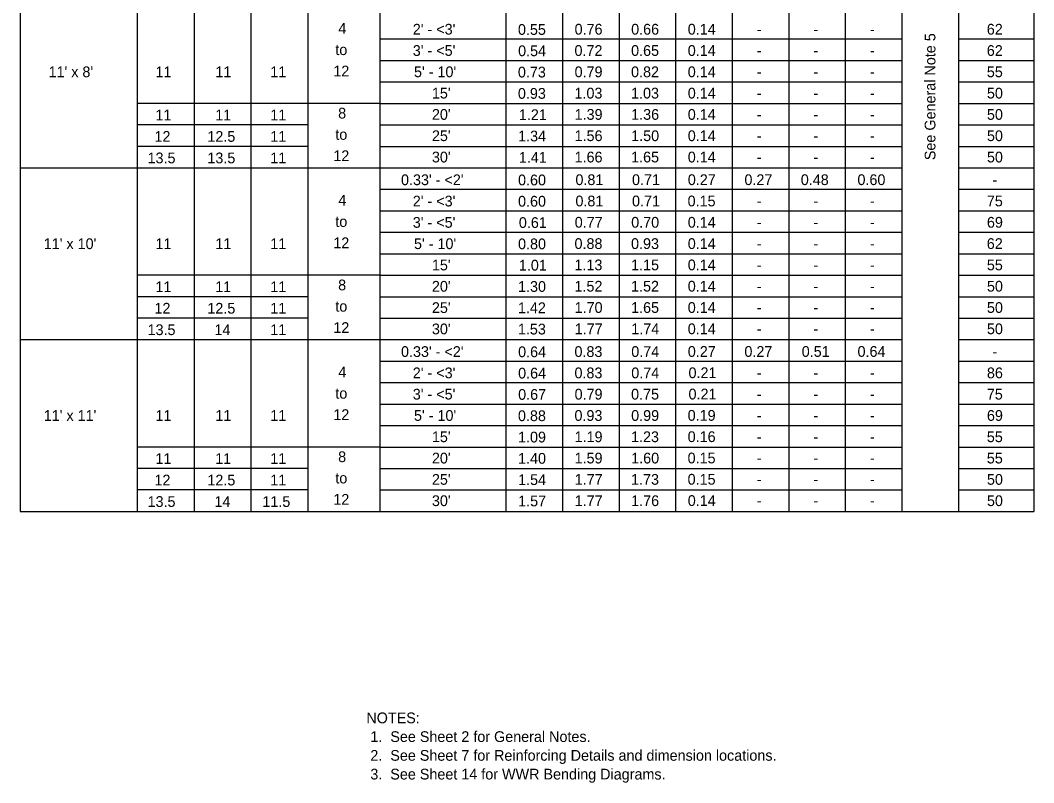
# Model space of a CAD drawing. Extents: x 10351.18 to 10353.4, y 76371.55 to 76372.62.
# Drawn here: x 10351.832 to 10352.427, y 76371.801 to 76372.249 of the extents above; entities that cross this region are included whole.
import ezdxf

# ---------------------------------------------------------------- set-up
doc = ezdxf.new("R2010")
doc.units = 0
doc.layers.add('AdhocPoint_dp', color=7, linetype='Continuous')
doc.layers.add('PlotBorder_dp', color=7, linetype='Continuous')

msp = doc.modelspace()

# ---------------------------------------------------------------- linework, layer by layer
at = {"layer": 'PlotBorder_dp'}
for p, q in [((10351.83244, 76372.53475), (10351.83244, 76371.96053)), ((10352.42718, 76372.53475), (10352.42718, 76371.96053)), ((10351.90108, 76372.51488), (10351.90108, 76371.96053)), ((10352.04352, 76372.51488), (10352.04352, 76371.96053)), ((10352.1174, 76372.51488), (10352.1174, 76371.96053)), ((10352.38299, 76372.51488), (10352.38299, 76371.96053)), ((10351.93444, 76372.50228), (10351.93444, 76371.96053)), ((10351.9678, 76372.50228), (10351.9678, 76371.96053)), ((10352.00116, 76372.50228), (10352.00116, 76371.96053)), ((10352.1506, 76372.47713), (10352.1506, 76371.96053)), ((10352.1838, 76372.47713), (10352.1838, 76371.96053)), ((10352.217, 76372.47713), (10352.217, 76371.96053)), ((10352.2502, 76372.47713), (10352.2502, 76371.96053)), ((10352.28339, 76372.47713), (10352.28339, 76371.96053)), ((10352.28339, 76372.47713), (10352.28339, 76371.96053)), ((10352.31659, 76372.47713), (10352.31659, 76371.96053)), ((10352.34979, 76372.47713), (10352.34979, 76371.96053)), ((10352.04352, 76372.23773), (10352.34979, 76372.23773)), ((10352.38299, 76372.23772), (10352.42718, 76372.23772)), ((10352.04352, 76372.22513), (10352.34979, 76372.22513)), ((10352.38299, 76372.22512), (10352.42718, 76372.22512)), ((10352.04352, 76372.21253), (10352.34979, 76372.21253)), ((10352.38299, 76372.21252), (10352.42718, 76372.21252)), ((10352.04352, 76372.19993), (10351.90108, 76372.19993)), ((10352.04352, 76372.19993), (10352.34979, 76372.19993)), ((10352.38299, 76372.19992), (10352.42718, 76372.19992)), ((10352.00116, 76372.18733), (10351.90108, 76372.18733)), ((10352.04352, 76372.18733), (10352.34979, 76372.18733)), ((10352.38299, 76372.18732), (10352.42718, 76372.18732)), ((10352.00116, 76372.17473), (10351.90108, 76372.17473)), ((10352.04352, 76372.17473), (10352.34979, 76372.17473)), ((10352.38299, 76372.17472), (10352.42718, 76372.17472)), ((10351.83244, 76372.16213), (10352.34979, 76372.16213)), ((10352.04414, 76372.16212), (10352.11631, 76372.16212)), ((10352.04414, 76372.16212), (10352.11631, 76372.16212)), ((10352.38299, 76372.16212), (10352.42718, 76372.16212)), ((10352.04352, 76372.14953), (10352.34979, 76372.14953)), ((10352.38299, 76372.14952), (10352.42718, 76372.14952)), ((10352.04352, 76372.13693), (10352.34979, 76372.13693)), ((10352.38299, 76372.13692), (10352.42718, 76372.13692)), ((10352.04352, 76372.12433), (10352.34979, 76372.12433)), ((10352.38299, 76372.12432), (10352.42718, 76372.12432)), ((10352.04352, 76372.11173), (10352.34979, 76372.11173)), ((10352.38299, 76372.11172), (10352.42718, 76372.11172)), ((10352.04352, 76372.09913), (10351.90108, 76372.09913)), ((10352.04352, 76372.09913), (10352.34979, 76372.09913)), ((10352.38299, 76372.09912), (10352.42718, 76372.09912)), ((10352.00116, 76372.08653), (10351.90108, 76372.08653)), ((10352.04352, 76372.08653), (10352.34979, 76372.08653)), ((10352.38299, 76372.08652), (10352.42718, 76372.08652)), ((10352.00116, 76372.07393), (10351.90108, 76372.07393)), ((10352.04352, 76372.07393), (10352.34979, 76372.07393)), ((10352.38299, 76372.07392), (10352.42718, 76372.07392)), ((10351.83244, 76372.06133), (10352.34979, 76372.06133)), ((10352.04414, 76372.06132), (10352.11631, 76372.06132)), ((10352.04414, 76372.06132), (10352.11631, 76372.06132)), ((10352.04414, 76372.06132), (10352.11631, 76372.06132)), ((10352.38299, 76372.06132), (10352.42718, 76372.06132)), ((10352.04352, 76372.04873), (10352.34979, 76372.04873)), ((10352.38299, 76372.04872), (10352.42718, 76372.04872)), ((10352.04352, 76372.03613), (10352.34979, 76372.03613)), ((10352.38299, 76372.03612), (10352.42718, 76372.03612)), ((10352.04352, 76372.02353), (10352.34979, 76372.02353)), ((10352.38299, 76372.02352), (10352.42718, 76372.02352)), ((10352.04352, 76372.01093), (10352.34979, 76372.01093)), ((10352.38299, 76372.01092), (10352.42718, 76372.01092)), ((10352.04352, 76371.99833), (10351.90108, 76371.99833)), ((10352.04352, 76371.99833), (10352.34979, 76371.99833)), ((10352.38299, 76371.99832), (10352.42718, 76371.99832)), ((10352.00116, 76371.98573), (10351.90108, 76371.98573)), ((10352.04352, 76371.98573), (10352.34979, 76371.98573)), ((10352.38299, 76371.98572), (10352.42718, 76371.98572)), ((10352.00116, 76371.97313), (10351.90108, 76371.97313)), ((10352.04352, 76371.97313), (10352.34979, 76371.97313)), ((10352.38299, 76371.97312), (10352.42718, 76371.97312)), ((10351.83244, 76371.96053), (10352.42718, 76371.96053)), ((10352.04414, 76371.96052), (10352.11631, 76371.96052))]:
    msp.add_line(p, q, dxfattribs=at)

# ---------------------------------------------------------------- texts
at = {"layer": 'AdhocPoint_dp'}
msp.add_text('See General Note 5', height=0.0063, rotation=90, dxfattribs=at).set_placement((10352.36949, 76372.16663))
for s, p in [('11', (10351.91176, 76372.18999)), ('11', (10351.94685, 76372.18999)), ('11', (10351.97914, 76372.18999)), ('12', (10351.91119, 76372.17739)), ('12.5', (10351.94224, 76372.17739)), ('11', (10351.97914, 76372.17739)), ('13.5', (10351.90714, 76372.16479)), ('13.5', (10351.94224, 76372.16479)), ('11', (10351.97914, 76372.16479)), ('11', (10351.91176, 76372.08919)), ('11', (10351.94685, 76372.08919)), ('11', (10351.97914, 76372.08919)), ('12', (10351.91119, 76372.07659)), ('12.5', (10351.94224, 76372.07659)), ('11', (10351.97914, 76372.07659)), ('13.5', (10351.90714, 76372.06399)), ('14', (10351.94641, 76372.06399)), ('11', (10351.97914, 76372.06399)), ('11', (10351.91176, 76371.98839)), ('11', (10351.94685, 76371.98839)), ('11', (10351.97914, 76371.98839)), ('12', (10351.91119, 76371.97579)), ('12.5', (10351.94224, 76371.97579)), ('11', (10351.97914, 76371.97579)), ('13.5', (10351.90714, 76371.96319)), ('14', (10351.94641, 76371.96319)), ('11.5', (10351.97452, 76371.96319))]:
    msp.add_text(s, height=0.0063, dxfattribs=at).set_placement(p)
at = {"layer": 'PlotBorder_dp'}
for s, p in [('4', (10352.0191, 76372.24078)), ("2' - <3'", (10352.06278, 76372.2403)), ('0.55', (10352.1245, 76372.24014)), ('0.76', (10352.15774, 76372.2403)), ('0.66', (10352.19094, 76372.2403)), ('0.14', (10352.22416, 76372.2403)), ('62', (10352.39964, 76372.2403)), ('-', (10352.26467, 76372.2403)), ('-', (10352.29788, 76372.2403)), ('-', (10352.33106, 76372.2403)), ('to', (10352.01732, 76372.22828)), ("3' - <5'", (10352.06278, 76372.2278)), ('0.54', (10352.1246, 76372.22764)), ('0.72', (10352.15768, 76372.2278)), ('0.65', (10352.1909, 76372.2278)), ('0.14', (10352.22416, 76372.2278)), ('62', (10352.39964, 76372.2278)), ('-', (10352.26467, 76372.2278)), ('-', (10352.29788, 76372.2278)), ('-', (10352.33106, 76372.2278)), ("11' x 8'", (10351.84905, 76372.2153)), ('11', (10351.91182, 76372.2153)), ('11', (10351.94691, 76372.2153)), ('11', (10351.97915, 76372.2153)), ('12', (10352.01615, 76372.21578)), ("5' - 10'", (10352.06349, 76372.2153)), ('0.73', (10352.12447, 76372.21514)), ('0.79', (10352.15774, 76372.2153)), ('0.82', (10352.19088, 76372.2153)), ('0.14', (10352.22416, 76372.2153)), ('55', (10352.39967, 76372.2153)), ('-', (10352.26467, 76372.2153)), ('-', (10352.29788, 76372.2153)), ('-', (10352.33106, 76372.2153)), ("15'", (10352.07401, 76372.2028)), ('1.03', (10352.15767, 76372.2028)), ('1.03', (10352.19087, 76372.2028)), ('0.14', (10352.22416, 76372.2028)), ('50', (10352.39972, 76372.2028)), ('0.93', (10352.12447, 76372.20264)), ('-', (10352.26467, 76372.2028)), ('-', (10352.29788, 76372.2028)), ('-', (10352.33106, 76372.2028)), ('8', (10352.01899, 76372.19106)), ("20'", (10352.07401, 76372.1903)), ('1.21', (10352.12504, 76372.19014)), ('1.39', (10352.15774, 76372.1903)), ('1.36', (10352.19094, 76372.1903)), ('0.14', (10352.22416, 76372.1903)), ('-', (10352.26467, 76372.1903)), ('-', (10352.29788, 76372.1903)), ('-', (10352.33106, 76372.1903)), ('50', (10352.39972, 76372.1903)), ('to', (10352.01732, 76372.17856)), ("25'", (10352.07401, 76372.1778)), ('1.34', (10352.1246, 76372.17764)), ('1.56', (10352.15774, 76372.1778)), ('1.50', (10352.19096, 76372.1778)), ('0.14', (10352.22416, 76372.1778)), ('-', (10352.26467, 76372.1778)), ('-', (10352.29788, 76372.1778)), ('-', (10352.33106, 76372.1778)), ('50', (10352.39972, 76372.1778)), ('12', (10352.01615, 76372.16606)), ("30'", (10352.07401, 76372.1653)), ('1.41', (10352.12504, 76372.16514)), ('1.66', (10352.15774, 76372.1653)), ('1.65', (10352.1909, 76372.1653)), ('0.14', (10352.22416, 76372.1653)), ('-', (10352.26467, 76372.1653)), ('-', (10352.29788, 76372.1653)), ('-', (10352.33106, 76372.1653)), ('50', (10352.39972, 76372.1653)), ("0.33' - <2'", (10352.05588, 76372.15196)), ('0.60', (10352.12456, 76372.15186)), ('0.81', (10352.15824, 76372.15202)), ('0.71', (10352.19144, 76372.15202)), ('0.27', (10352.22418, 76372.15202)), ('0.27', (10352.25741, 76372.15202)), ('0.48', (10352.29049, 76372.15202)), ('0.60', (10352.32374, 76372.15202)), ('-', (10352.40298, 76372.15202)), ('4', (10352.0191, 76372.13998)), ("2' - <3'", (10352.06278, 76372.13946)), ('0.60', (10352.12456, 76372.13936)), ('0.81', (10352.15824, 76372.13952)), ('0.71', (10352.19144, 76372.13952)), ('0.15', (10352.22406, 76372.13952)), ('75', (10352.39967, 76372.13952)), ('-', (10352.26467, 76372.13952)), ('-', (10352.29788, 76372.13952)), ('-', (10352.33106, 76372.13952)), ('to', (10352.01732, 76372.12748)), ("3' - <5'", (10352.06278, 76372.12696)), ('0.61', (10352.12504, 76372.12686)), ('0.77', (10352.15782, 76372.12702)), ('0.70', (10352.19096, 76372.12702)), ('0.14', (10352.22416, 76372.12702)), ('69', (10352.39971, 76372.12702)), ('-', (10352.26467, 76372.12702)), ('-', (10352.29788, 76372.12702)), ('-', (10352.33106, 76372.12702)), ("11' x 10'", (10351.84622, 76372.11446)), ('11', (10351.91182, 76372.11446)), ('11', (10351.94691, 76372.11446)), ('11', (10351.97915, 76372.11446)), ('12', (10352.01615, 76372.11498)), ("5' - 10'", (10352.06349, 76372.11446)), ('0.80', (10352.12456, 76372.11436)), ('0.88', (10352.15769, 76372.11452)), ('0.93', (10352.19087, 76372.11452)), ('0.14', (10352.22416, 76372.11452)), ('62', (10352.39964, 76372.11452)), ('-', (10352.26467, 76372.11452)), ('-', (10352.29788, 76372.11452)), ('-', (10352.33106, 76372.11452)), ("15'", (10352.07401, 76372.10196)), ('1.01', (10352.12504, 76372.10186)), ('1.13', (10352.15767, 76372.10202)), ('1.15', (10352.1909, 76372.10202)), ('0.14', (10352.22416, 76372.10202)), ('55', (10352.39967, 76372.10202)), ('-', (10352.26467, 76372.10202)), ('-', (10352.29788, 76372.10202)), ('-', (10352.33106, 76372.10202)), ('8', (10352.01899, 76372.09026)), ("20'", (10352.07401, 76372.08946)), ('1.30', (10352.12456, 76372.08936)), ('1.52', (10352.15768, 76372.08952)), ('1.52', (10352.19088, 76372.08952)), ('0.14', (10352.22416, 76372.08952)), ('-', (10352.26467, 76372.08952)), ('-', (10352.29788, 76372.08952)), ('-', (10352.33106, 76372.08952)), ('50', (10352.39972, 76372.08952)), ('to', (10352.01732, 76372.07776)), ("25'", (10352.07401, 76372.07696)), ('1.42', (10352.12448, 76372.07686)), ('1.70', (10352.15775, 76372.07702)), ('1.65', (10352.1909, 76372.07702)), ('0.14', (10352.22416, 76372.07702)), ('-', (10352.26467, 76372.07702)), ('-', (10352.29788, 76372.07702)), ('-', (10352.33106, 76372.07702)), ('50', (10352.39972, 76372.07702)), ('12', (10352.01615, 76372.06526)), ("30'", (10352.07401, 76372.06446)), ('1.53', (10352.12447, 76372.06436)), ('1.77', (10352.15782, 76372.06452)), ('1.74', (10352.191, 76372.06452)), ('0.14', (10352.22416, 76372.06452)), ('-', (10352.26467, 76372.06452)), ('-', (10352.29788, 76372.06452)), ('-', (10352.33106, 76372.06452)), ('50', (10352.39972, 76372.06452)), ("0.33' - <2'", (10352.05588, 76372.05118)), ('0.64', (10352.1246, 76372.05103)), ('0.83', (10352.15767, 76372.05118)), ('0.74', (10352.191, 76372.05118)), ('0.27', (10352.22418, 76372.05124)), ('0.27', (10352.25741, 76372.05124)), ('0.51', (10352.29104, 76372.05124)), ('0.64', (10352.32378, 76372.05124)), ('-', (10352.40298, 76372.05118)), ('4', (10352.0191, 76372.03918)), ("2' - <3'", (10352.06278, 76372.03868)), ('0.64', (10352.1246, 76372.03853)), ('0.83', (10352.15767, 76372.03868)), ('0.74', (10352.191, 76372.03868)), ('0.21', (10352.2246, 76372.03874)), ('86', (10352.39971, 76372.03868)), ('-', (10352.26467, 76372.03874)), ('-', (10352.29788, 76372.03874)), ('-', (10352.33106, 76372.03874)), ('to', (10352.01732, 76372.02668)), ("3' - <5'", (10352.06278, 76372.02618)), ('0.67', (10352.12462, 76372.02603)), ('0.79', (10352.15774, 76372.02618)), ('0.75', (10352.1909, 76372.02618)), ('0.21', (10352.2246, 76372.02624)), ('75', (10352.39967, 76372.02618)), ('-', (10352.26467, 76372.02624)), ('-', (10352.29788, 76372.02624)), ('-', (10352.33106, 76372.02624)), ("11' x 11'", (10351.84622, 76372.01368)), ('11', (10351.91182, 76372.01368)), ('11', (10351.94691, 76372.01368)), ('11', (10351.97915, 76372.01368)), ('12', (10352.01615, 76372.01418)), ("5' - 10'", (10352.06349, 76372.01368)), ('0.88', (10352.1245, 76372.01353)), ('0.93', (10352.15767, 76372.01368)), ('0.99', (10352.19094, 76372.01368)), ('0.19', (10352.2241, 76372.01374)), ('69', (10352.39971, 76372.01368)), ('-', (10352.26467, 76372.01374)), ('-', (10352.29788, 76372.01374)), ('-', (10352.33106, 76372.01374)), ("15'", (10352.07401, 76372.00118)), ('1.09', (10352.12454, 76372.00103)), ('1.19', (10352.15774, 76372.00118)), ('1.23', (10352.19087, 76372.00118)), ('0.16', (10352.2241, 76372.00124)), ('55', (10352.39967, 76372.00118)), ('-', (10352.26467, 76372.00124)), ('-', (10352.29788, 76372.00124)), ('-', (10352.33106, 76372.00124)), ('8', (10352.01899, 76371.98946)), ("20'", (10352.07401, 76371.98868)), ('1.59', (10352.15774, 76371.98868)), ('1.60', (10352.19096, 76371.98868)), ('0.15', (10352.22406, 76371.98874)), ('55', (10352.39967, 76371.98868)), ('1.40', (10352.12456, 76371.98853)), ('-', (10352.26467, 76371.98874)), ('-', (10352.29788, 76371.98874)), ('-', (10352.33106, 76371.98874)), ('to', (10352.01732, 76371.97696)), ("25'", (10352.07401, 76371.97618)), ('1.54', (10352.1246, 76371.97603)), ('1.77', (10352.15782, 76371.97618)), ('1.73', (10352.19087, 76371.97618)), ('0.15', (10352.22406, 76371.97624)), ('-', (10352.26467, 76371.97624)), ('-', (10352.29788, 76371.97624)), ('-', (10352.33106, 76371.97624)), ('50', (10352.39972, 76371.97618)), ('12', (10352.01615, 76371.96446)), ("30'", (10352.07401, 76371.96368)), ('1.57', (10352.12462, 76371.96353)), ('1.77', (10352.15782, 76371.96368)), ('1.76', (10352.19094, 76371.96368)), ('0.14', (10352.22416, 76371.96374)), ('-', (10352.26467, 76371.96374)), ('-', (10352.29788, 76371.96374)), ('-', (10352.33106, 76371.96374)), ('50', (10352.39972, 76371.96368)), ('NOTES:', (10352.03554, 76371.83627)), (' 1.  See Sheet 2 for General Notes.', (10352.03554, 76371.82527)), (' 2.  See Sheet 7 for Reinforcing Details and dimension locations.', (10352.03554, 76371.81427)), (' 3.  See Sheet 14 for WWR Bending Diagrams.', (10352.03554, 76371.80327))]:
    msp.add_text(s, height=0.0063, dxfattribs=at).set_placement(p)

doc.saveas('drawing.dxf')
